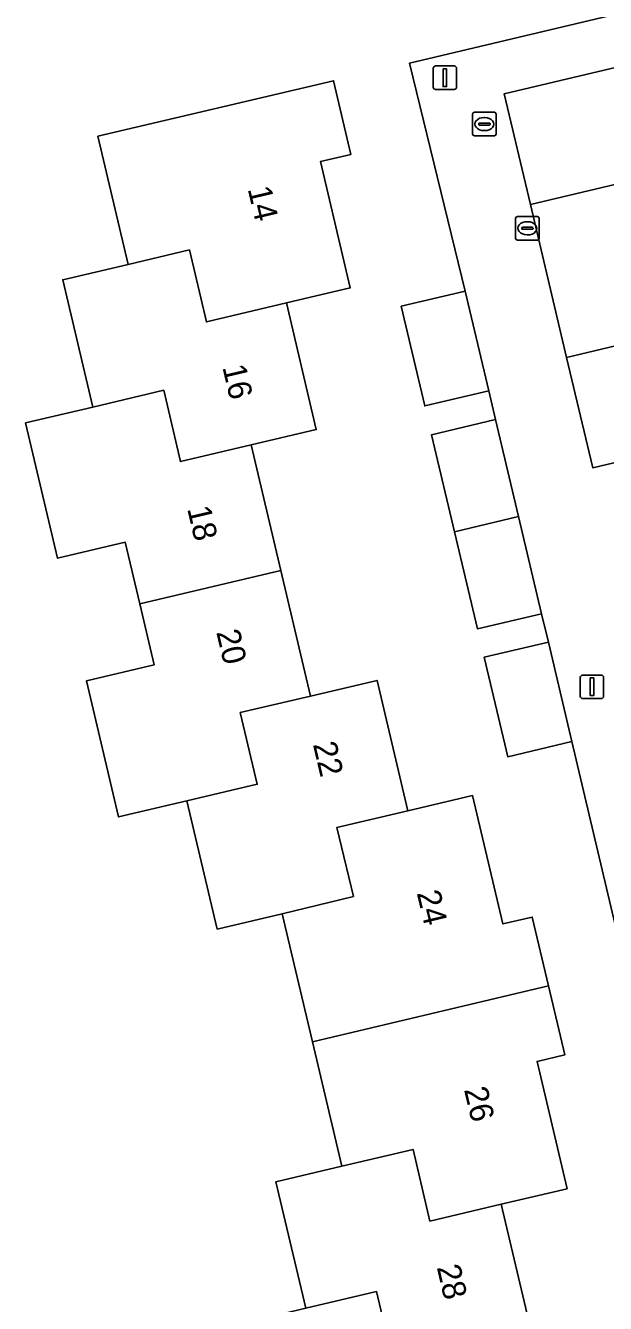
# Model space of a CAD drawing. Extents: x 158031 to 159244, y 380104 to 381214.
# Drawn here: x 158640.7 to 158665.3, y 380430.2 to 380484.6 of the extents above; entities that cross this region are included whole.
import ezdxf

# ---------------------------------------------------------------- set-up
doc = ezdxf.new("R2010")
doc.units = 0
for name, color, linetype in [('IMGEO_Erf', 7, 'Continuous'), ('IMGEO_Hek', 7, 'Continuous'), ('IMGEO_Lichtmast', 7, 'Continuous'), ('IMGEO_Pand', 7, 'Continuous'), ('IMGEO_Pand_nummerreeks', 7, 'Continuous'), ('IMGEO_Parkeervlak_open', 7, 'Continuous'), ('IMGEO_Rijbaan_lokaal_open', 7, 'Continuous'), ('IMGEO_Rioolput', 7, 'Continuous'), ('IMGEO_Voetpad_open', 7, 'Continuous')]:
    doc.layers.add(name, color=color, linetype=linetype)

msp = doc.modelspace()

# ---------------------------------------------------------------- linework, layer by layer
at = {"layer": 'IMGEO_Erf'}
for points in [[(158657.929, 380467.167), (158660.654, 380467.811), (158660.368, 380469.037), (158657.644, 380468.391), (158656.639, 380472.629), (158659.364, 380473.275), (158656.99, 380482.96), (158690.712, 380490.978), (158683.218, 380504.501), (158679.067, 380511.942)], [(158652.581, 380430.028), (158651.313, 380435.406), (158654.117, 380436.067), (158652.87, 380441.358), (158651.587, 380446.802), (158648.821, 380446.15), (158647.536, 380451.601), (158644.632, 380450.916), (158643.267, 380456.707), (158646.139, 380457.384), (158645.527, 380459.98), (158644.911, 380462.597), (158642.034, 380461.919), (158640.677, 380467.674), (158643.536, 380468.348), (158642.26, 380473.759), (158645.036, 380474.413), (158643.753, 380479.857), (158653.767, 380482.217), (158654.505, 380479.084), (158653.209, 380478.779), (158654.475, 380473.409), (158651.763, 380472.77), (158653.031, 380467.39), (158650.27, 380466.739), (158651.528, 380461.4), (158652.787, 380456.06), (158655.613, 380456.726), (158656.92, 380451.18), (158659.675, 380451.829), (158660.962, 380446.369), (158662.207, 380446.662), (158662.898, 380443.731), (158663.589, 380440.803), (158662.415, 380440.526), (158663.691, 380435.112), (158660.885, 380434.451), (158662.171, 380428.997)], [(158669.709, 380429.443), (158669.428, 380430.652), (158666.701, 380430.014), (158665.714, 380434.238), (158668.44, 380434.875), (158663.891, 380454.12), (158661.166, 380453.48), (158660.172, 380457.711), (158662.898, 380458.351), (158662.603, 380459.561), (158659.878, 380458.917), (158658.903, 380463.042), (158657.929, 380467.167)]]:
    msp.add_lwpolyline(points, dxfattribs=at)
at = {"layer": 'IMGEO_Hek'}
msp.add_lwpolyline([(158690.712, 380490.978), (158656.99, 380482.96)], dxfattribs=at)
at = {"layer": 'IMGEO_Lichtmast'}
for p, q in [((158658.102, 380482.847), (158658.892, 380482.847)), ((158658.892, 380482.847), (158658.102, 380482.847)), ((158658.002, 380481.947), (158658.002, 380482.747)), ((158658.002, 380482.747), (158658.002, 380481.947)), ((158658.992, 380482.747), (158658.992, 380481.947)), ((158658.992, 380481.947), (158658.992, 380482.747)), ((158658.892, 380481.847), (158658.102, 380481.847)), ((158658.102, 380481.847), (158658.892, 380481.847)), ((158664.252, 380456.052), (158664.252, 380456.852)), ((158664.252, 380456.852), (158664.252, 380456.052)), ((158664.352, 380456.952), (158665.142, 380456.952)), ((158665.142, 380456.952), (158664.352, 380456.952)), ((158665.242, 380456.852), (158665.242, 380456.052)), ((158665.242, 380456.052), (158665.242, 380456.852)), ((158665.142, 380455.952), (158664.352, 380455.952)), ((158664.352, 380455.952), (158665.142, 380455.952))]:
    msp.add_line(p, q, dxfattribs=at)
for points in [[(158658.422, 380482.722), (158658.572, 380482.722), (158658.572, 380481.972), (158658.422, 380481.972), (158658.422, 380482.722)], [(158664.672, 380456.827), (158664.822, 380456.827), (158664.822, 380456.077), (158664.672, 380456.077), (158664.672, 380456.827)]]:
    msp.add_lwpolyline(points, dxfattribs=at)
for centre, start, end in [((158658.102, 380482.747), 90, 180), ((158658.102, 380482.747), 90, 180), ((158658.892, 380482.747), 0, 90), ((158658.892, 380482.747), 360, 90), ((158658.102, 380481.947), 180, 270), ((158658.102, 380481.947), 180, 270), ((158658.892, 380481.947), 270, 0), ((158658.892, 380481.947), 270, 0), ((158664.352, 380456.852), 90, 180), ((158664.352, 380456.852), 90, 180), ((158665.142, 380456.852), 0, 90), ((158665.142, 380456.852), 360, 90), ((158664.352, 380456.052), 180, 270), ((158664.352, 380456.052), 180, 270), ((158665.142, 380456.052), 270, 0), ((158665.142, 380456.052), 270, 0)]:
    msp.add_arc(centre, 0.1, start, end, dxfattribs=at)
at = {"layer": 'IMGEO_Pand'}
for points in [[(158651.763, 380472.77), (158654.475, 380473.409), (158653.209, 380478.779), (158654.505, 380479.084), (158653.767, 380482.217), (158643.753, 380479.857), (158645.036, 380474.413), (158647.641, 380475.027), (158648.361, 380471.968)], [(158651.763, 380472.77), (158648.361, 380471.968), (158647.641, 380475.027), (158645.036, 380474.413), (158642.26, 380473.759), (158643.536, 380468.348), (158646.546, 380469.058), (158647.26, 380466.029), (158650.27, 380466.739), (158653.031, 380467.39)], [(158659.364, 380473.275), (158656.639, 380472.629), (158657.644, 380468.391), (158660.368, 380469.037)], [(158650.27, 380466.739), (158647.26, 380466.029), (158646.546, 380469.058), (158643.536, 380468.348), (158640.677, 380467.674), (158642.034, 380461.919), (158644.911, 380462.597), (158645.527, 380459.98), (158651.528, 380461.4)], [(158661.628, 380463.686), (158660.654, 380467.811), (158657.929, 380467.167), (158658.903, 380463.042)], [(158661.628, 380463.686), (158658.903, 380463.042), (158659.878, 380458.917), (158662.603, 380459.561)], [(158645.527, 380459.98), (158646.139, 380457.384), (158643.267, 380456.707), (158644.632, 380450.916), (158647.536, 380451.601), (158650.522, 380452.305), (158649.802, 380455.356), (158652.787, 380456.06), (158651.528, 380461.4)], [(158662.898, 380458.351), (158660.172, 380457.711), (158661.166, 380453.48), (158663.891, 380454.12)], [(158656.92, 380451.18), (158655.613, 380456.726), (158652.787, 380456.06), (158649.802, 380455.356), (158650.522, 380452.305), (158647.536, 380451.601), (158648.821, 380446.15), (158651.587, 380446.802), (158654.609, 380447.539), (158653.905, 380450.47)], [(158652.87, 380441.358), (158662.898, 380443.731), (158662.207, 380446.662), (158660.962, 380446.369), (158659.675, 380451.829), (158656.92, 380451.18), (158653.905, 380450.47), (158654.609, 380447.539), (158651.587, 380446.802)], [(158654.117, 380436.067), (158657.142, 380436.78), (158657.859, 380433.738), (158660.885, 380434.451), (158663.691, 380435.112), (158662.415, 380440.526), (158663.589, 380440.803), (158662.898, 380443.731), (158652.87, 380441.358)], [(158654.117, 380436.067), (158651.313, 380435.406), (158652.581, 380430.028), (158655.595, 380430.739), (158656.331, 380427.62), (158659.346, 380428.331), (158662.171, 380428.997), (158660.885, 380434.451), (158657.859, 380433.738), (158657.142, 380436.78)], [(158652.581, 380430.028), (158649.738, 380429.357), (158651.12, 380423.496), (158654.011, 380424.177), (158654.656, 380421.442), (158655.771, 380421.705), (158660.637, 380422.852), (158659.346, 380428.331), (158656.331, 380427.62), (158655.595, 380430.739)]]:
    msp.add_lwpolyline(points, close=True, dxfattribs=at)
at = {"layer": 'IMGEO_Parkeervlak_open'}
for points in [[(158662.133, 380476.955), (158691.886, 380484.012), (158690.819, 380488.741), (158661.014, 380481.657)], [(158693.513, 380477.568), (158663.668, 380470.457), (158664.789, 380465.758), (158694.616, 380472.843)]]:
    msp.add_lwpolyline(points, close=True, dxfattribs=at)
at = {"layer": 'IMGEO_Rijbaan_lokaal_open'}
msp.add_lwpolyline([(158693.513, 380477.568), (158693.449, 380477.869), (158693.363, 380477.855), (158691.886, 380484.012), (158662.133, 380476.955), (158663.668, 380470.457)], close=True, dxfattribs=at)
at = {"layer": 'IMGEO_Rioolput'}
for p, q in [((158659.675, 380479.953), (158659.675, 380480.805)), ((158659.75, 380480.879), (158660.602, 380480.879)), ((158660.163, 380480.659), (158660.188, 380480.659)), ((158660.676, 380480.805), (158660.676, 380479.953)), ((158659.934, 380480.373), (158659.934, 380480.385)), ((158660.372, 380480.336), (158659.974, 380480.336)), ((158659.977, 380480.422), (158660.375, 380480.422)), ((158660.418, 380480.385), (158660.418, 380480.373)), ((158660.602, 380479.879), (158659.75, 380479.879)), ((158660.186, 380480.099), (158660.161, 380480.099)), ((158661.501, 380475.519), (158661.501, 380476.371)), ((158661.576, 380476.445), (158662.428, 380476.445)), ((158662.502, 380476.371), (158662.502, 380475.519)), ((158661.76, 380475.939), (158661.76, 380475.951)), ((158662.198, 380475.902), (158661.8, 380475.902)), ((158661.803, 380475.988), (158662.201, 380475.988)), ((158661.989, 380476.225), (158662.014, 380476.225)), ((158662.244, 380475.951), (158662.244, 380475.939)), ((158662.428, 380475.445), (158661.576, 380475.445)), ((158662.012, 380475.665), (158661.987, 380475.665))]:
    msp.add_line(p, q, dxfattribs=at)
for points in [[(158659.675, 380479.953), (158659.675, 380480.805)], [(158659.75, 380480.879), (158660.602, 380480.879)], [(158660.676, 380480.805), (158660.676, 380479.953)], [(158660.602, 380479.879), (158659.75, 380479.879)], [(158661.501, 380475.519), (158661.501, 380476.371)], [(158661.576, 380476.445), (158662.428, 380476.445)], [(158662.502, 380476.371), (158662.502, 380475.519)], [(158662.428, 380475.445), (158661.576, 380475.445)]]:
    msp.add_lwpolyline(points, dxfattribs=at)
for centre, radius, start, end in [((158659.752, 380480.803), 0.0765, 91.552, 178.448), ((158659.752, 380480.803), 0.0765, 91.552, 178.448), ((158660.6, 380480.803), 0.0765, 1.552, 88.448), ((158660.6, 380480.803), 0.0765, 1.552, 88.448), ((158659.974, 380480.382), 0.0403, 85.8775, 175.7526), ((158659.971, 380480.372), 0.0366, 178.938, 274.7102), ((158660.375, 380480.379), 0.043, 264.8664, 352.4533), ((158660.379, 380480.384), 0.0386, 1.7309, 96.639), ((158659.752, 380479.955), 0.0765, 181.552, 268.448), ((158659.752, 380479.955), 0.0765, 181.552, 268.448), ((158660.6, 380479.955), 0.0765, 271.552, 358.448), ((158660.6, 380479.955), 0.0765, 271.552, 358.448), ((158661.578, 380476.369), 0.0765, 91.552, 178.448), ((158661.578, 380476.369), 0.0765, 91.552, 178.448), ((158662.426, 380476.369), 0.0765, 1.552, 88.448), ((158662.426, 380476.369), 0.0765, 1.552, 88.448), ((158661.8, 380475.948), 0.0403, 85.8775, 175.7526), ((158661.797, 380475.938), 0.0366, 178.938, 274.7102), ((158662.201, 380475.945), 0.043, 264.8664, 352.4533), ((158662.205, 380475.95), 0.0386, 1.7309, 96.639), ((158661.578, 380475.521), 0.0765, 181.552, 268.448), ((158661.578, 380475.521), 0.0765, 181.552, 268.448), ((158662.426, 380475.521), 0.0765, 271.552, 358.448), ((158662.426, 380475.521), 0.0765, 271.552, 358.448)]:
    msp.add_arc(centre, radius, start, end, dxfattribs=at)
for centre, major_axis, ratio, start_param, end_param in [((158660.162, 380480.379), (-0.387, 0.002), 0.722429, 4.712389, 7.853982), ((158660.187, 380480.379), (-0.39, 0.002), 0.717154, 1.570796, 4.712389), ((158661.988, 380475.945), (-0.387, 0.002), 0.722429, 4.712389, 7.853982), ((158662.013, 380475.945), (-0.39, 0.002), 0.717154, 1.570796, 4.712389)]:
    msp.add_ellipse(centre, major_axis=major_axis, ratio=ratio, start_param=start_param, end_param=end_param, dxfattribs=at)
at = {"layer": 'IMGEO_Voetpad_open'}
for points in [[(158690.712, 380490.978), (158656.99, 380482.96), (158659.364, 380473.275), (158660.368, 380469.037), (158660.654, 380467.811), (158661.628, 380463.686), (158662.603, 380459.561), (158662.898, 380458.351), (158663.891, 380454.12), (158668.44, 380434.875), (158669.428, 380430.652), (158669.709, 380429.443)], [(158694.616, 380472.843), (158664.789, 380465.758), (158663.668, 380470.457), (158662.133, 380476.955), (158661.014, 380481.657), (158690.819, 380488.741)]]:
    msp.add_lwpolyline(points, dxfattribs=at)

# ---------------------------------------------------------------- texts
at = {"layer": 'IMGEO_Pand_nummerreeks'}
for s, rotation, p in [('14', 283.2655, (158650.112, 380477.624)), ('16', 283.2619, (158649.036, 380470.044)), ('18', 283.2623, (158647.54, 380464.03)), ('20', 283.2623, (158648.777, 380458.779)), ('22', 283.2607, (158652.884, 380454.008)), ('24', 283.5084, (158657.296, 380447.686)), ('26', 283.5084, (158659.304, 380439.328)), ('28', 283.2675, (158658.147, 380431.773))]:
    msp.add_text(s, height=1, rotation=rotation, dxfattribs=at).set_placement(p)

doc.saveas('drawing.dxf')
